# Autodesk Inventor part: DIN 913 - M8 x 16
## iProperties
Created: 2006-02
Part Number: DIN 913 - M8 x 16
Material: Steel, Mild
Description: Hexagon Socket Set Screw
Document SubType Name: Modeling
Standard: DIN 913
Designer: Andy Moles
Standards Organization: DIN
Language: en-US
Size Designation: M8 x 16
Categories: <MemberInstance><Categories><Category DisplayName="Fasteners" InternalName="e4da775c-781d-43d5-af7c-5136215cf5a6" Mnemonic="FSTN"><Category DisplayName="Bolts"
Density: 7.86 g/cm^3
Author: Andy Moles
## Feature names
1. Body [Revolution]
2. Slot [Extrusion]
3. Chamfer1
4. Chamfer2
